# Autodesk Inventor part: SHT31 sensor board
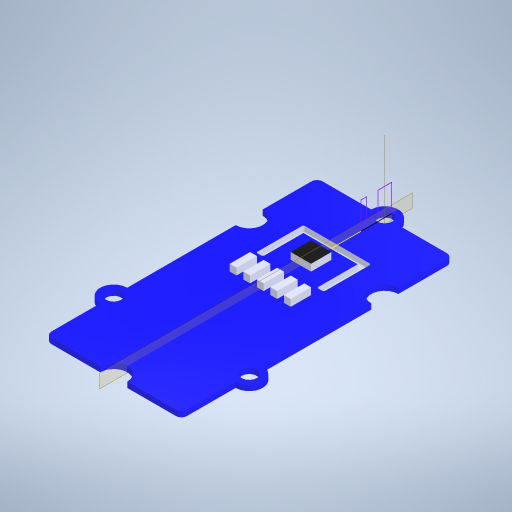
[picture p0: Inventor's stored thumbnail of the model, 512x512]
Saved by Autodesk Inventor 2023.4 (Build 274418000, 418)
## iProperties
Created: 2019-06
Part Number: SHT31 sensor board
Material: Générique
Document SubType Name: Modeling
Designer: mel
Density: 1 g/cm^3
Appearance: Par défaut
Author: mel
Sending System: SolidWorks 2018
Last Author: Hazel
Last Saved: 2019-07-03
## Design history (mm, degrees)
feature "SMDs"
node "Plan de construction1"
  node "Axe de construction1"
sketch "Esquisse1"
  geometry: L1 (0, 0.8)-(0, 8) reference; L2 (0, 3.538)-(4, 3.538); L3 (4, -1)-(0, -1); L4 (0, -1)-(0, 3.538); L5 (4, 2.687)-(1, 2.687); L6 (1, 2.687)-(1, 1); L7 (1, 1)-(4, 1); L8 (4, 3.538)-(4, 2.687); L9 (4, 1)-(4, -1); 1 further point
  constraints: 16 end point, 4 parallel, 3 perpendicular, 2 horizontal, 1 point on line
node "Solide1"
other parameters: "d0" = 0
